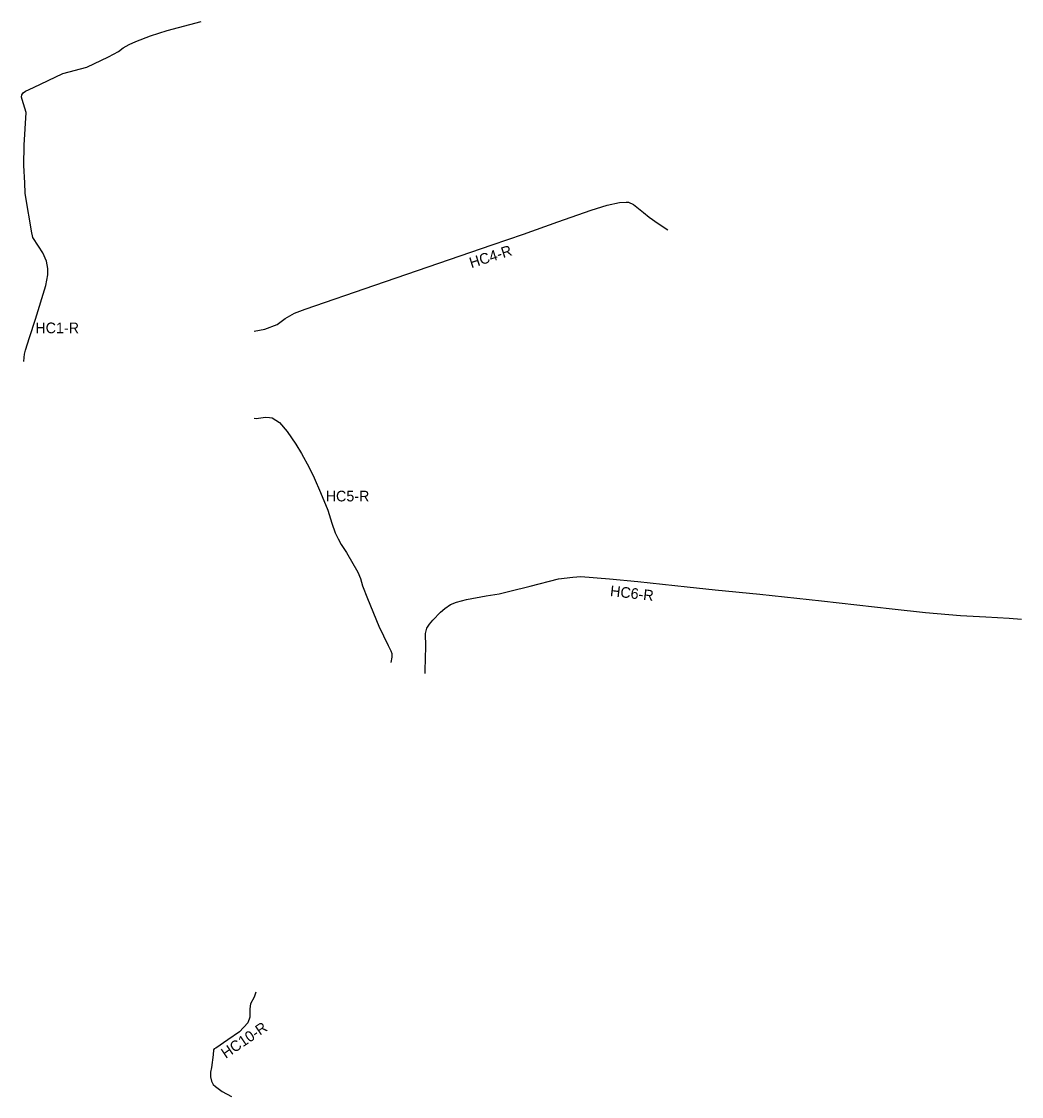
# Model space of a CAD drawing. Extents: x -567508 to -565449, y -1138888 to -1136673.
import ezdxf

# ---------------------------------------------------------------- set-up
doc = ezdxf.new("R2010")
doc.units = 0
doc.layers.add('03_PC_NAVRH', color=7, linetype='Continuous')
doc.layers.add('03_PC_POPIS_NAVRH', color=7, linetype='Continuous')

msp = doc.modelspace()

# ---------------------------------------------------------------- linework, layer by layer
at = {"layer": '03_PC_NAVRH'}
for points in [[(-567502.8, -1137373.7), (-567502.2, -1137365.6), (-567501.5, -1137358.7), (-567500, -1137350.2), (-567491.2, -1137324.4), (-567478.8, -1137286.6), (-567458.1, -1137217.4), (-567453.5, -1137194.9), (-567453.4, -1137182.3), (-567456.6, -1137166.7), (-567464.3, -1137149.6), (-567472.8, -1137136.3), (-567484.8, -1137117.9), (-567487.1, -1137105), (-567489.8, -1137087.8), (-567496.2, -1137052.3), (-567500.3, -1137026.8), (-567501, -1137005.9), (-567503, -1136969.8), (-567502.1, -1136928.1), (-567498, -1136860.6), (-567506.8, -1136834.2), (-567507.9, -1136829), (-567507, -1136824.4), (-567504.6, -1136820.1), (-567499.8, -1136817), (-567483.2, -1136808.9), (-567422.5, -1136780.7), (-567373.1, -1136767.1), (-567328.9, -1136745.8), (-567308.5, -1136735.1), (-567298.3, -1136727.3), (-567286.5, -1136720.9), (-567272.4, -1136714.2), (-567242, -1136702.6), (-567207.8, -1136691.8), (-567137.7, -1136673.3)], [(-567028.6, -1137311.3), (-567007, -1137307.2), (-566981.7, -1137297.3), (-566965.3, -1137285.1), (-566945.5, -1137274), (-566923.5, -1137265.9), (-566780.4, -1137216.2), (-566538.6, -1137133.4), (-566474.4, -1137111.1), (-566403.4, -1137085.6), (-566334.6, -1137061.7), (-566302.2, -1137051.7), (-566276.7, -1137046.2), (-566262.9, -1137045.1), (-566257.9, -1137045.6), (-566247.7, -1137050.2), (-566226.9, -1137066.7), (-566215.3, -1137076.5), (-566197.2, -1137089.3), (-566176.7, -1137102.5)], [(-567028.7, -1137490.1), (-567025, -1137490.8), (-567005.5, -1137488.4), (-566997.3, -1137488.7), (-566991.5, -1137489.5), (-566976.8, -1137499), (-566960.7, -1137517.8), (-566942.9, -1137544), (-566931.2, -1137563.3), (-566915.4, -1137591.7), (-566905.3, -1137613.2), (-566891.9, -1137643.2), (-566876.9, -1137680), (-566868.8, -1137706.9), (-566861.8, -1137726.7), (-566855.6, -1137739.2), (-566849.4, -1137750.2), (-566838.7, -1137767), (-566815.3, -1137807.2), (-566809.9, -1137820.8), (-566805.8, -1137835.5), (-566795.7, -1137861.7), (-566771.9, -1137918.6), (-566752.8, -1137958.3), (-566747.1, -1137969.3), (-566745.3, -1137974.8), (-566745.4, -1137982.6), (-566747.4, -1137993.8)], [(-566677, -1138016.4), (-566676.8, -1138010.1), (-566675.4, -1137960.4), (-566676.3, -1137933.8), (-566673.3, -1137923.2), (-566667.9, -1137914.8), (-566661, -1137906.7), (-566645, -1137889.8), (-566636.4, -1137882.2), (-566624.5, -1137874.4), (-566612.1, -1137869.1), (-566591.4, -1137863.5), (-566551.2, -1137856.5), (-566524.5, -1137852.1), (-566502.6, -1137846.7), (-566460.6, -1137836.1), (-566402.1, -1137821.6), (-566372.9, -1137817.5), (-566356.2, -1137816.7), (-566297.2, -1137821.1), (-566238.8, -1137826.7), (-566137.5, -1137837.6), (-566079.2, -1137843.6), (-565987.4, -1137852.8), (-565860.7, -1137866.3), (-565714.9, -1137883), (-565646.3, -1137890.8), (-565574.6, -1137897.1), (-565522.2, -1137899.5), (-565474.3, -1137902.3), (-565448.8, -1137904.2)], [(-567025.2, -1138672.3), (-567028.6, -1138682.9), (-567036.3, -1138696.6), (-567037.9, -1138707), (-567037.6, -1138713.8), (-567037.9, -1138724.2), (-567041.6, -1138736.1), (-567059.1, -1138754.2), (-567083.1, -1138770.8), (-567107.9, -1138787.7), (-567111.1, -1138789.4), (-567112.4, -1138791.4), (-567113.1, -1138801.6), (-567116.6, -1138828), (-567118.5, -1138837.6), (-567118.9, -1138846.8), (-567117, -1138856.1), (-567113.1, -1138862.9), (-567108.6, -1138866.9), (-567094.6, -1138877.1), (-567075.4, -1138887.5)]]:
    msp.add_lwpolyline(points, dxfattribs=at)

# ---------------------------------------------------------------- texts
at = {"layer": '03_PC_POPIS_NAVRH'}
for s, rotation, p in [('HC4-R', 17.7044, (-566581.6, -1137181.6)), ('HC6-R', 353.4004, (-566296.8, -1137856.6)), ('HC10-R', 34.2056, (-567087.3, -1138810.3))]:
    msp.add_text(s, height=22, rotation=rotation, dxfattribs=at).set_placement(p)
for s, p in [('HC1-R', (-567479.4, -1137315.4)), ('HC5-R', (-566881.5, -1137661.8))]:
    msp.add_text(s, height=22, dxfattribs=at).set_placement(p)

doc.saveas('drawing.dxf')
